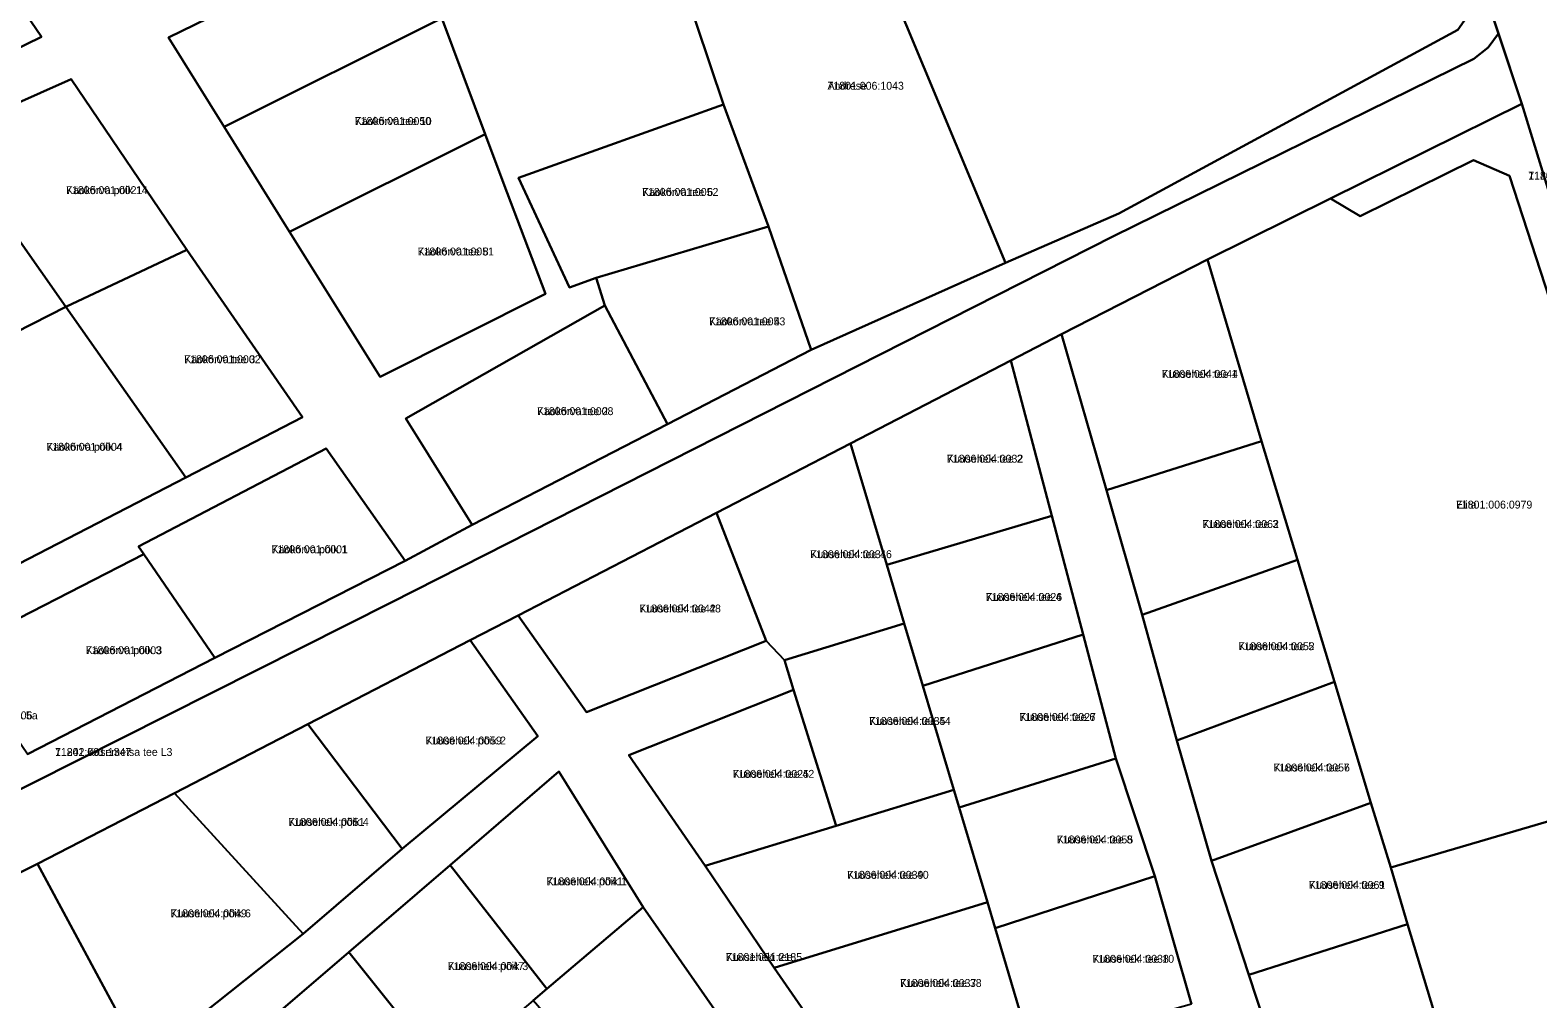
# Model space of a CAD drawing. Extents: x 529768 to 552006, y 6562269 to 6580975.
# Drawn here: x 538402.9 to 538689.4, y 6570171.8 to 6570355.9 of the extents above; entities that cross this region are included whole.
import ezdxf

# ---------------------------------------------------------------- set-up
doc = ezdxf.new("R2010")
doc.units = 0
for name, color, linetype in [('L_AADRESS', 7, 'Continuous'), ('PIIR', 7, 'Continuous'), ('TUNNUS', 7, 'Continuous')]:
    doc.layers.add(name, color=color, linetype=linetype)

msp = doc.modelspace()

# ---------------------------------------------------------------- linework, layer by layer
at = {"layer": 'PIIR'}
for points in [[(539116.8, 6569078.23), (539058.81, 6569187.43), (539044.1, 6569219.87), (539023.92, 6569264.22), (539022.98, 6569267.6), (539007.05, 6569317.26), (538933.83, 6569559.82), (538866.18, 6569768.99), (538833.03, 6569872.74), (538821.73, 6569908.63), (538824.56, 6569909.51), (538776.18, 6570052.37), (538740.03, 6570166.99), (538725.15, 6570215.43), (538686.31, 6570341.92), (538679.27, 6570363.29), (538664.27, 6570409.69), (538652.67, 6570445.8), (538641.86, 6570479.33), (538630.82, 6570513.57), (538630.09, 6570515.96), (538577.14, 6570690.88)], [(538383.47, 6570344.15), (538405.03, 6570354.67), (538381.89, 6570388.53)], [(538474.1, 6570376.53), (538429.15, 6570354.53), (538439.72, 6570337.55), (538452.16, 6570317.61), (538469.35, 6570290.03), (538500.79, 6570305.79), (538492.83, 6570326.84), (538489.31, 6570336.19), (538481.1, 6570358.19)], [(538524.33, 6570372.42), (538534.64, 6570341.82), (538495.64, 6570327.89), (538505.35, 6570307.02), (538510.45, 6570308.88), (538512.04, 6570303.6), (538474.26, 6570282.15), (538486.88, 6570261.92), (538474.14, 6570255.06), (538459.09, 6570276.39), (538423.46, 6570257.81), (538424.47, 6570256.32), (538388.87, 6570238.11)], [(538402.34, 6570218.34), (538437.92, 6570236.62), (538474.14, 6570255.06), (538486.88, 6570261.92), (538523.95, 6570281.03), (538551.31, 6570295.16), (538588.21, 6570311.7), (538609.72, 6570321.06), (538674.15, 6570355.97), (538679.27, 6570363.29), (538681.9, 6570355.27), (538679.95, 6570352.61), (538677.24, 6570350.49), (538608.75, 6570316.79), (538471.44, 6570247.18), (538369.28, 6570195.7)], [(538369.28, 6570195.7), (538471.44, 6570247.18), (538608.75, 6570316.79), (538677.24, 6570350.49), (538679.95, 6570352.61), (538681.9, 6570355.27), (538686.31, 6570341.92), (538649.98, 6570323.94), (538626.59, 6570312.36), (538598.88, 6570298.15), (538589.2, 6570293.15), (538558.75, 6570277.39), (538533.26, 6570264.21), (538495.58, 6570244.71), (538486.48, 6570240), (538455.65, 6570224.05), (538430.31, 6570210.94), (538404.27, 6570197.47), (538353.26, 6570172.13)], [(538623.58, 6570170.8), (538616.59, 6570195.11), (538609.16, 6570217.49), (538602.94, 6570241.08), (538596.99, 6570263.61), (538589.2, 6570293.15), (538598.88, 6570298.15), (538607.39, 6570268.48), (538614.18, 6570244.83), (538620.75, 6570220.92), (538627.38, 6570198.03), (538634.48, 6570176.38), (538642.01, 6570153.47)], [(538424.38, 6570160.03), (538454.76, 6570184.16), (538473.53, 6570200.34), (538499.32, 6570221.77), (538486.48, 6570240), (538495.58, 6570244.71), (538508.55, 6570226.3), (538542.7, 6570239.87), (538546.19, 6570236.21), (538547.95, 6570230.58), (538516.6, 6570218.12), (538531.14, 6570197.08), (538544.26, 6570177.72), (538557.94, 6570157.98)], [(538537.27, 6570163.54), (538519.34, 6570189.26), (538503.35, 6570215.03), (538482.66, 6570197.24), (538463.4, 6570180.68), (538445.2, 6570165.04)]]:
    msp.add_lwpolyline(points, dxfattribs=at)
for points in [[(538566.29, 6570364.26), (538664.27, 6570409.69), (538679.27, 6570363.29), (538674.15, 6570355.97), (538609.72, 6570321.06), (538588.21, 6570311.7)], [(538520.57, 6570383.39), (538553.18, 6570395.56), (538566.29, 6570364.26), (538588.21, 6570311.7), (538551.31, 6570295.16), (538543.18, 6570318.63), (538534.64, 6570341.82), (538524.33, 6570372.42)], [(538360.88, 6570376.8), (538381.89, 6570388.53), (538405.03, 6570354.67), (538383.47, 6570344.15)], [(538429.15, 6570354.53), (538474.1, 6570376.53), (538481.1, 6570358.19), (538439.72, 6570337.55)], [(538439.72, 6570337.55), (538481.1, 6570358.19), (538489.31, 6570336.19), (538452.16, 6570317.61)], [(538389.33, 6570248.66), (538432.43, 6570270.9), (538454.63, 6570282.38), (538432.64, 6570314.17), (538410.65, 6570346.63), (538386.72, 6570335.94), (538365.02, 6570325.15), (538329.22, 6570307.3), (538343.66, 6570285.31), (538358.1, 6570263.31), (538373.42, 6570240.43)], [(538386.72, 6570335.94), (538410.65, 6570346.63), (538432.64, 6570314.17), (538409.64, 6570303.32)], [(538534.64, 6570341.82), (538543.18, 6570318.63), (538510.45, 6570308.88), (538505.35, 6570307.02), (538495.64, 6570327.89)], [(538686.31, 6570341.92), (538725.15, 6570215.43), (538721.07, 6570214.24), (538683.98, 6570328.26), (538677.14, 6570331.24), (538655.59, 6570320.58), (538649.98, 6570323.94)], [(538365.02, 6570325.15), (538386.72, 6570335.94), (538409.64, 6570303.32), (538387.11, 6570291.85), (538379.82, 6570303.14)], [(538452.16, 6570317.61), (538489.31, 6570336.19), (538492.83, 6570326.84), (538500.79, 6570305.79), (538469.35, 6570290.03)], [(538626.59, 6570312.36), (538649.98, 6570323.94), (538655.59, 6570320.58), (538677.14, 6570331.24), (538683.98, 6570328.26), (538721.07, 6570214.24), (538661.45, 6570196.78), (538657.67, 6570209.08), (538650.72, 6570232.05), (538643.71, 6570255.26), (538636.89, 6570277.8)], [(538512.04, 6570303.6), (538510.45, 6570308.88), (538543.18, 6570318.63), (538551.31, 6570295.16), (538523.95, 6570281.03)], [(538454.63, 6570282.38), (538432.43, 6570270.9), (538409.64, 6570303.32), (538432.64, 6570314.17)], [(538626.59, 6570312.36), (538636.89, 6570277.8), (538607.39, 6570268.48), (538598.88, 6570298.15)], [(538389.33, 6570248.66), (538373.66, 6570271.22), (538394.24, 6570281.69), (538387.11, 6570291.85), (538409.64, 6570303.32), (538432.43, 6570270.9)], [(538512.04, 6570303.6), (538523.95, 6570281.03), (538486.88, 6570261.92), (538474.26, 6570282.15)], [(538596.99, 6570263.61), (538565.63, 6570254.31), (538558.75, 6570277.39), (538589.2, 6570293.15)], [(538568.95, 6570243.18), (538546.19, 6570236.21), (538542.7, 6570239.87), (538533.26, 6570264.21), (538558.75, 6570277.39), (538565.63, 6570254.31)], [(538607.39, 6570268.48), (538636.89, 6570277.8), (538643.71, 6570255.26), (538614.18, 6570244.83)], [(538474.14, 6570255.06), (538437.92, 6570236.62), (538424.47, 6570256.32), (538423.46, 6570257.81), (538459.09, 6570276.39)], [(538508.55, 6570226.3), (538495.58, 6570244.71), (538533.26, 6570264.21), (538542.7, 6570239.87)], [(538602.94, 6570241.08), (538572.5, 6570231.29), (538568.95, 6570243.18), (538565.63, 6570254.31), (538596.99, 6570263.61)], [(538388.87, 6570238.11), (538424.47, 6570256.32), (538437.92, 6570236.62), (538402.34, 6570218.34)], [(538614.18, 6570244.83), (538643.71, 6570255.26), (538650.72, 6570232.05), (538620.75, 6570220.92)], [(538578.39, 6570211.56), (538556, 6570204.7), (538547.95, 6570230.58), (538546.19, 6570236.21), (538568.95, 6570243.18), (538572.5, 6570231.29)], [(538609.16, 6570217.49), (538579.38, 6570208.21), (538578.39, 6570211.56), (538572.5, 6570231.29), (538602.94, 6570241.08)], [(538499.32, 6570221.77), (538473.53, 6570200.34), (538455.65, 6570224.05), (538486.48, 6570240)], [(538620.75, 6570220.92), (538650.72, 6570232.05), (538657.67, 6570209.08), (538627.38, 6570198.03)], [(538531.14, 6570197.08), (538516.6, 6570218.12), (538547.95, 6570230.58), (538556, 6570204.7)], [(538473.53, 6570200.34), (538454.76, 6570184.16), (538430.31, 6570210.94), (538455.65, 6570224.05)], [(538616.59, 6570195.11), (538586.24, 6570185.23), (538584.76, 6570190.18), (538579.38, 6570208.21), (538609.16, 6570217.49)], [(538503.35, 6570215.03), (538519.34, 6570189.26), (538501.05, 6570173.71), (538482.66, 6570197.24)], [(538584.76, 6570190.18), (538544.26, 6570177.72), (538531.14, 6570197.08), (538556, 6570204.7), (538578.39, 6570211.56), (538579.38, 6570208.21)], [(538671.59, 6570163.04), (538664.64, 6570186.01), (538661.45, 6570196.78), (538721.07, 6570214.24), (538733.76, 6570166.03), (538734.75, 6570162.29), (538719.96, 6570149.63), (538689.47, 6570123.62), (538684.74, 6570119.58), (538682.87, 6570125.76)], [(538454.76, 6570184.16), (538424.38, 6570160.03), (538404.27, 6570197.47), (538430.31, 6570210.94)], [(538627.38, 6570198.03), (538657.67, 6570209.08), (538661.45, 6570196.78), (538664.64, 6570186.01), (538634.48, 6570176.38)], [(538397.76, 6570097.07), (538381.56, 6570124.4), (538367.66, 6570147.6), (538353.26, 6570172.13), (538404.27, 6570197.47), (538424.38, 6570160.03), (538429.12, 6570151.22), (538443.37, 6570124.68), (538452.62, 6570107.46), (538405.14, 6570085.22)], [(538482.66, 6570197.24), (538501.05, 6570173.71), (538498.46, 6570171.51), (538482, 6570157.52), (538463.4, 6570180.68)], [(538623.58, 6570170.8), (538593.09, 6570162.25), (538591.34, 6570168.14), (538586.24, 6570185.23), (538616.59, 6570195.11)], [(538537.27, 6570163.54), (538518.95, 6570147.82), (538498.46, 6570171.51), (538501.05, 6570173.71), (538519.34, 6570189.26)], [(538591.34, 6570168.14), (538557.94, 6570157.98), (538544.26, 6570177.72), (538584.76, 6570190.18), (538586.24, 6570185.23)], [(538642.01, 6570153.47), (538634.48, 6570176.38), (538664.64, 6570186.01), (538671.59, 6570163.04)], [(538463.4, 6570180.68), (538482, 6570157.52), (538480.55, 6570156.29), (538463.71, 6570141.97), (538445.2, 6570165.04)]]:
    msp.add_lwpolyline(points, close=True, dxfattribs=at)

# ---------------------------------------------------------------- texts
at = {"layer": 'L_AADRESS'}
for s, p in [('Andrese', (538554.39, 6570344.61)), ('Käokõrva tee 10', (538464.55, 6570337.9)), ('11241 Kasemetsa-Kiisa tee', (538687.56, 6570327.54)), ('Käokõrva põik 14', (538409.68, 6570324.77)), ('Käokõrva tee 6', (538519.15, 6570324.42)), ('Käokõrva tee 8', (538476.49, 6570313.11)), ('Käokõrva tee 4', (538531.86, 6570299.83)), ('Käokõrva tee 3', (538432.14, 6570292.63)), ('Kuuseheki tee 1', (538617.89, 6570289.85)), ('Käokõrva tee 2', (538499.19, 6570282.76)), ('Käokõrva põik 4', (538405.94, 6570275.99)), ('Kuuseheki tee 2', (538577.08, 6570273.73)), ('Elita', (538673.83, 6570265)), ('Kuuseheki tee 3', (538625.66, 6570261.32)), ('Käokõrva põik 1', (538448.73, 6570256.51)), ('Kuuseheki tee 46', (538551.11, 6570255.58)), ('Kuuseheki tee 4', (538584.47, 6570247.45)), ('Kuuseheki tee 48', (538518.62, 6570245.26)), ('Käokõrva põik 3', (538413.42, 6570237.33)), ('Kuuseheki tee 5', (538632.46, 6570238.09)), ('Käokõrva põik 5a', (538388.78, 6570224.95)), ('Kuuseheki tee 6', (538590.88, 6570224.65)), ('Kuuseheki tee 44', (538562.29, 6570223.88)), ('Kuuseheki põik 2', (538477.99, 6570220.17)), ('11242 Kasemetsa tee L3', (538407.58, 6570217.99)), ('Kuuseheki tee 42', (538536.36, 6570213.83)), ('Kuuseheki tee 7', (538639.16, 6570215.04)), ('Kuuseheki põik 4', (538451.92, 6570204.7)), ('Kuuseheki tee 8', (538597.97, 6570201.36)), ('Kuuseheki põik 1', (538501, 6570193.39)), ('Kuuseheki tee 40', (538558.11, 6570194.64)), ('Kuuseheki tee 9', (538645.88, 6570192.73)), ('Kuuseheki põik 6', (538429.52, 6570187.32)), ('Kuuseheki tee', (538535.05, 6570179.02)), ('Kuuseheki tee 10', (538604.75, 6570178.68)), ('Kuuseheki põik 3', (538482.22, 6570177.29)), ('Kuuseheki tee 38', (538568.17, 6570174.08))]:
    msp.add_text(s, height=1.5, dxfattribs=at).set_placement(p)
at = {"layer": 'TUNNUS'}
for s, p in [('71801:006:1043', (538554.39, 6570344.61)), ('71806:001:0050', (538464.55, 6570337.9)), ('71801:006:0980', (538687.56, 6570327.54)), ('71806:001:0021', (538409.68, 6570324.77)), ('71806:001:0052', (538519.15, 6570324.42)), ('71806:001:0051', (538476.49, 6570313.11)), ('71806:001:0053', (538531.86, 6570299.83)), ('71806:001:0002', (538432.14, 6570292.63)), ('71806:004:0044', (538617.89, 6570289.85)), ('71806:001:0008', (538499.19, 6570282.76)), ('71806:001:0004', (538405.94, 6570275.99)), ('71806:004:0032', (538577.08, 6570273.73)), ('71801:006:0979', (538673.83, 6570265)), ('71806:004:0062', (538625.66, 6570261.32)), ('71806:001:0001', (538448.73, 6570256.51)), ('71806:004:0031', (538551.11, 6570255.58)), ('71806:004:0026', (538584.47, 6570247.45)), ('71806:004:0042', (538518.62, 6570245.26)), ('71806:001:0003', (538413.42, 6570237.33)), ('71806:004:0052', (538632.46, 6570238.09)), ('71806:001:0006', (538388.78, 6570224.95)), ('71806:004:0027', (538590.88, 6570224.65)), ('71806:004:0035', (538562.29, 6570223.88)), ('71806:004:0059', (538477.99, 6570220.17)), ('71801:001:1347', (538407.58, 6570217.99)), ('71806:004:0025', (538536.36, 6570213.83)), ('71806:004:0056', (538639.16, 6570215.04)), ('71806:004:0051', (538451.92, 6570204.7)), ('71806:004:0055', (538597.97, 6570201.36)), ('71806:004:0041', (538501, 6570193.39)), ('71806:004:0039', (538558.11, 6570194.64)), ('71806:004:0061', (538645.88, 6570192.73)), ('71806:004:0049', (538429.52, 6570187.32)), ('71801:001:2185', (538535.05, 6570179.02)), ('71806:004:0038', (538604.75, 6570178.68)), ('71806:004:0047', (538482.22, 6570177.29)), ('71806:004:0037', (538568.17, 6570174.08))]:
    msp.add_text(s, height=1.5, dxfattribs=at).set_placement(p)

doc.saveas('drawing.dxf')
